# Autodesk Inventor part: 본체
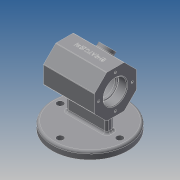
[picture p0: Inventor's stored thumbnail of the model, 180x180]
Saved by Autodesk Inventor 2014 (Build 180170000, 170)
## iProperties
Created: 2021-02
Part Number: 본체
Material: Generic
Document SubType Name: Modeling
Designer: kb542
Density: 1 g/cm^3
Appearance: Default
Author: kb542
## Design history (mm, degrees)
sketch "스케치2" dims "d5" = 58
  geometry: L1 (-12.012, 29)-(12.012, 29); L2 (12.012, 29)-(29, 12.012); L3 (29, 12.012)-(29, -12.012); L4 (29, -12.012)-(12.012, -29); L5 (12.012, -29)-(-12.012, -29); L6 (-12.012, -29)-(-29, -12.012); L7 (-29, -12.012)-(-29, 12.012); L8 (-29, 12.012)-(-12.012, 29); 5 further points
  constraints: 16 end point, 3 coincident, 1 horizontal, 1 midpoint, 20 other
extrude "돌출1" new body sketch "스케치2" stored distance "d6" = 70; taper "d7" = 0 deg
sketch "스케치1"
  geometry: L1 (-35, 0)-(35, 0); L2 (-35, 16)-(-23, 16); L3 (-23, 16)-(-23, 14); L4 (-23, 14)-(-20, 14); L5 (-20, 14)-(-20, 22); L6 (-20, 22)-(20, 22); L7 (20, 22)-(20, 14); L8 (20, 14)-(23, 14); L9 (23, 14)-(23, 16); L10 (23, 16)-(35, 16); L11 (-35, 12.012)-(-35, -12.012) reference; L12 (35, -12.012)-(35, 12.012) reference; L13 (-35, 16)-(-35, 0); L14 (-35, 29)-(-35, 12.012) reference; L15 (35, 0)-(35, 16); L16 (35, 12.012)-(35, 29) reference; 2 further points
  constraints: 24 end point, 5 collinear, 5 parallel, 1 coincident, 1 horizontal, 1 midpoint, 1 perpendicular
  dimensions: "d1" = 40 distance between parallel lines of L7 L5; "d3" = 3 distance between parallel lines of L5 L3; "d4" = 3 distance between parallel lines of L9 L7; "d9" = 44 diameter of L6 L1; "d10" = 32 diameter of L2 L1; "d11" = 28 diameter of L4 L1; "d12" = 32 diameter of L10 L1; "d13" = 28 diameter of L8 L1; "d16" = 12 distance between parallel lines of L3 L13
revolve "회전1" sketch "스케치1" stored, may be unused: angle "d14" = 90 deg
sketch "스케치3" dims "d15" = 46
  geometry: C1 r 16 at (0, 0) reference; 2 further points
  constraints: 2 vertical alignment, 2 other
hole "구멍1" sketch "스케치3" at (0, 23) diameter "d17" = 3.242; stored, may be unused: countersink angle "d21" = 90 deg, drill point angle "d23" = 118 deg; dims "d18" = 8, "d19" = 4, "d20" = 2, "d22" = 10
sketch "스케치4"
  geometry: L1 (0, -24.024)-(0, 0) reference; C1 r 10 at (35, -12.012); 2 further points
  constraints: 1 centre point, 1 horizontal alignment, 1 midpoint
  dimensions: "d27" = 35 distance from line of L1 C1.centre; "d33" = 20 diameter of C1
extrude "돌출2" join sketch "스케치4" distance "d28" = 5; taper "d29" = 0 deg
hole "구멍2" diameter "d37" = 10.917; stored, may be unused: countersink angle "d41" = 90 deg, drill point angle "d43" = 118 deg; dims "d35" = 10, "d36" = 10, "d38" = 6, "d39" = 16, "d40" = 2, "d42" = 8
node "작업 평면1"
sketch "스케치6" dims "d46" = 82
  geometry: C1 r 52 at (0, 0); C2 r 4.5 at (0, 41); C3 r 4.5 at (-41, 0); C4 r 4.5 at (0, -41); C5 r 4.5 at (41, 0); 1 further point
  constraints: 5 centre point, 2 vertical alignment, 1 coincident, 11 other
  dimensions: "d45" = 104 diameter of C1; "d47" = 9 diameter of C2; "d50" = 360 deg dimension on C1.centre C2.centre (derived)
extrude "돌출3" join sketch "스케치6" distance "d52" = 10; taper "d53" = 0 deg
sketch "스케치7"
  geometry: L1 (-28, 5)-(28, 5); L2 (28, 5)-(28, -5); L3 (28, -5)-(-28, -5); L4 (-28, -5)-(-28, 5); C1 r 52 at (0, 0) reference; 2 further points
  constraints: 8 end point, 2 midpoint, 2 parallel, 1 horizontal, 1 horizontal alignment, 1 perpendicular, 1 vertical alignment
  dimensions: "d54" = 10 distance between parallel lines of L3 L1; "d55" = 56 distance between parallel lines of L2 L4
extrude "돌출4" join sketch "스케치7" stored distance "d56" = 10; taper "d57" = 0 deg
chamfer "모따기1" distance "d58" = 1; stored, may be unused: second distance "d59" = 2, angle "d60" = 45 deg
chamfer "모따기2" distance "d61" = 1; stored, may be unused: second distance "d62" = 2, angle "d63" = 45 deg
chamfer "모따기3" distance "d64" = 1; stored, may be unused: second distance "d65" = 2, angle "d66" = 45 deg
fillet "모깎기1" dims "d67" = 0.3, "d68" = 3, "d69" = 1
fillet "모깎기2" dims "d70" = 3
sketch "스케치8"
  geometry: L1 (70, 23.196)-(70, 0) reference; L2 (70, -17.109)-(0, -17.109) reference; 2 further points
  constraints: 1 other
  dimensions: "d71" = 35 distance from line of L1 point (35, 11.891); "d72" = 29 distance from line of L2 point (35, 11.891)
feature "엠보싱1" sketch "스케치8" dims "d1" = 40, "d3" = 3, "d4" = 3, "d5" = 58, "d9" = 44, "d10" = 32, "d11" = 28, "d12" = 32, "d13" = 28, "d16" = 12, "d73" = 0.5, "d74" = 0
node "솔리드1"
pattern_circular "원형 패턴1" dims angle "d25" = 360 deg
mirror "대칭1"
other parameters: "d44" = -62
